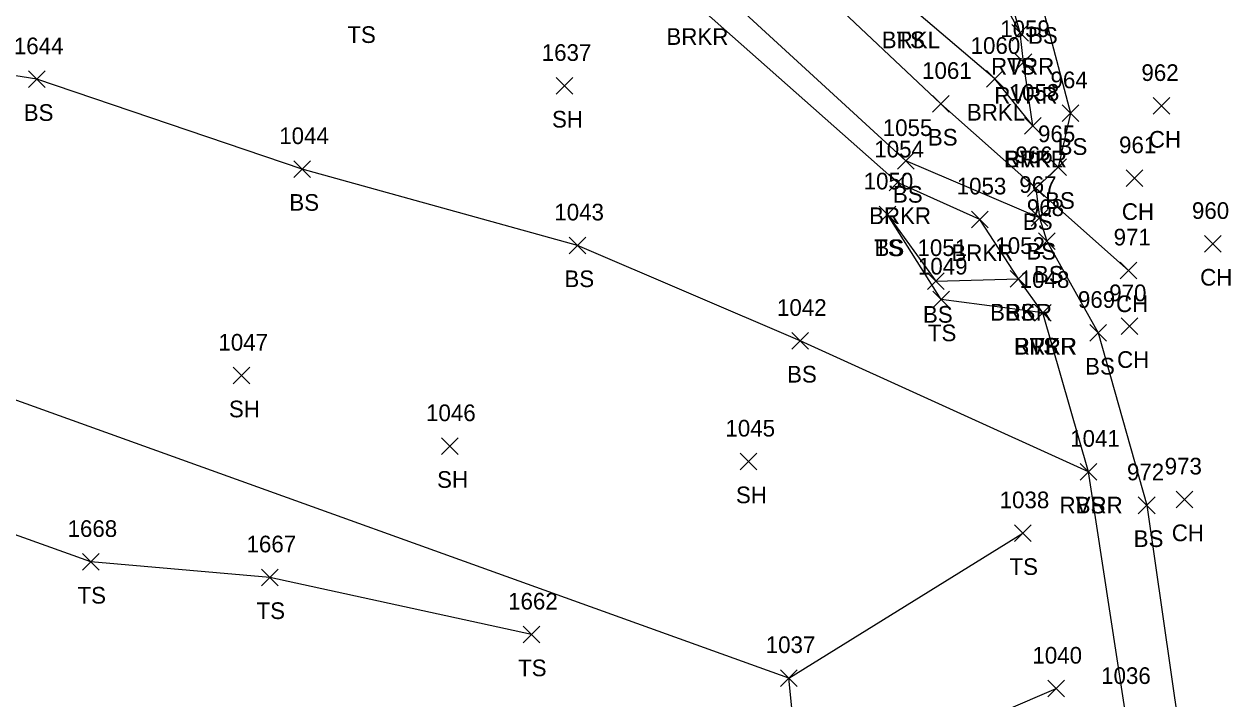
# Model space of a CAD drawing. Extents: x 1885914 to 1887218, y 756253 to 760620.
# Drawn here: x 1886519.5 to 1886664.7, y 759574 to 759655 of the extents above; entities that cross this region are included whole.
import ezdxf

# ---------------------------------------------------------------- set-up
doc = ezdxf.new("R2010")
doc.units = 0
for name, color, linetype in [('L_A', 7, 'Continuous'), ('L_I', 7, 'Continuous'), ('L_TIC', 7, 'Continuous'), ('LAWE', 7, 'Continuous'), ('LELB', 7, 'Continuous')]:
    doc.layers.add(name, color=color, linetype=linetype)

msp = doc.modelspace()

# ---------------------------------------------------------------- linework, layer by layer
at = {"layer": 'L_TIC'}
for points in [[(1886637.96, 759652.9), (1886639.96, 759654.9)], [(1886639.96, 759652.9), (1886637.96, 759654.9)], [(1886637.96, 759652.9), (1886639.96, 759654.9)], [(1886639.96, 759652.9), (1886637.96, 759654.9)], [(1886638.36, 759649.41), (1886640.36, 759651.41)], [(1886640.36, 759649.41), (1886638.36, 759651.41)], [(1886520.04, 759647.35), (1886522.04, 759649.35)], [(1886522.04, 759647.35), (1886520.04, 759649.35)], [(1886583.34, 759646.55), (1886585.34, 759648.55)], [(1886585.34, 759646.55), (1886583.34, 759648.55)], [(1886634.93, 759647.39), (1886636.93, 759649.39)], [(1886636.93, 759647.39), (1886634.93, 759649.39)], [(1886628.46, 759644.39), (1886630.46, 759646.39)], [(1886630.46, 759644.39), (1886628.46, 759646.39)], [(1886654.92, 759644.14), (1886656.92, 759646.14)], [(1886656.92, 759644.14), (1886654.92, 759646.14)], [(1886644.02, 759643.27), (1886646.02, 759645.27)], [(1886646.02, 759643.27), (1886644.02, 759645.27)], [(1886639.49, 759641.77), (1886641.49, 759643.77)], [(1886641.49, 759641.77), (1886639.49, 759643.77)], [(1886639.49, 759641.77), (1886641.49, 759643.77)], [(1886641.49, 759641.77), (1886639.49, 759643.77)], [(1886551.89, 759636.57), (1886553.89, 759638.57)], [(1886553.89, 759636.57), (1886551.89, 759638.57)], [(1886624.27, 759637.54), (1886626.27, 759639.54)], [(1886626.27, 759637.54), (1886624.27, 759639.54)], [(1886642.52, 759636.8), (1886644.52, 759638.8)], [(1886644.52, 759636.8), (1886642.52, 759638.8)], [(1886623.26, 759634.97), (1886625.26, 759636.97)], [(1886625.26, 759634.97), (1886623.26, 759636.97)], [(1886651.67, 759635.47), (1886653.67, 759637.47)], [(1886653.67, 759635.47), (1886651.67, 759637.47)], [(1886639.86, 759634.28), (1886641.86, 759636.28)], [(1886641.86, 759634.28), (1886639.86, 759636.28)], [(1886639.86, 759634.28), (1886641.86, 759636.28)], [(1886641.86, 759634.28), (1886639.86, 759636.28)], [(1886622.06, 759631.13), (1886624.06, 759633.13)], [(1886624.06, 759631.13), (1886622.06, 759633.13)], [(1886622.06, 759631.13), (1886624.06, 759633.13)], [(1886624.06, 759631.13), (1886622.06, 759633.13)], [(1886633.13, 759630.53), (1886635.13, 759632.53)], [(1886635.13, 759630.53), (1886633.13, 759632.53)], [(1886640.28, 759630.71), (1886642.28, 759632.71)], [(1886642.28, 759630.71), (1886640.28, 759632.71)], [(1886640.28, 759630.71), (1886642.28, 759632.71)], [(1886642.28, 759630.71), (1886640.28, 759632.71)], [(1886584.88, 759627.41), (1886586.88, 759629.41)], [(1886586.88, 759627.41), (1886584.88, 759629.41)], [(1886641.18, 759627.94), (1886643.18, 759629.94)], [(1886643.18, 759627.94), (1886641.18, 759629.94)], [(1886661.07, 759627.59), (1886663.07, 759629.59)], [(1886663.07, 759627.59), (1886661.07, 759629.59)], [(1886627.87, 759623.14), (1886629.87, 759625.14)], [(1886629.87, 759623.14), (1886627.87, 759625.14)], [(1886637.77, 759623.39), (1886639.77, 759625.39)], [(1886639.77, 759623.39), (1886637.77, 759625.39)], [(1886637.77, 759623.39), (1886639.77, 759625.39)], [(1886639.77, 759623.39), (1886637.77, 759625.39)], [(1886650.98, 759624.41), (1886652.98, 759626.41)], [(1886652.98, 759624.41), (1886650.98, 759626.41)], [(1886628.49, 759620.92), (1886630.49, 759622.92)], [(1886630.49, 759620.92), (1886628.49, 759622.92)], [(1886640.69, 759619.32), (1886642.69, 759621.32)], [(1886642.69, 759619.32), (1886640.69, 759621.32)], [(1886640.69, 759619.32), (1886642.69, 759621.32)], [(1886642.69, 759619.32), (1886640.69, 759621.32)], [(1886640.69, 759619.32), (1886642.69, 759621.32)], [(1886642.69, 759619.32), (1886640.69, 759621.32)], [(1886651.1, 759617.72), (1886653.1, 759619.72)], [(1886653.1, 759617.72), (1886651.1, 759619.72)], [(1886611.58, 759615.96), (1886613.58, 759617.96)], [(1886613.58, 759615.96), (1886611.58, 759617.96)], [(1886647.32, 759616.92), (1886649.32, 759618.92)], [(1886649.32, 759616.92), (1886647.32, 759618.92)], [(1886544.6, 759611.79), (1886546.6, 759613.79)], [(1886546.6, 759611.79), (1886544.6, 759613.79)], [(1886569.56, 759603.33), (1886571.56, 759605.33)], [(1886571.56, 759603.33), (1886569.56, 759605.33)], [(1886605.4, 759601.48), (1886607.4, 759603.48)], [(1886607.4, 759601.48), (1886605.4, 759603.48)], [(1886646.18, 759600.26), (1886648.18, 759602.26)], [(1886648.18, 759600.26), (1886646.18, 759602.26)], [(1886646.18, 759600.26), (1886648.18, 759602.26)], [(1886648.18, 759600.26), (1886646.18, 759602.26)], [(1886657.66, 759596.93), (1886659.66, 759598.93)], [(1886659.66, 759596.93), (1886657.66, 759598.93)], [(1886653.14, 759596.23), (1886655.14, 759598.23)], [(1886655.14, 759596.23), (1886653.14, 759598.23)], [(1886638.28, 759592.88), (1886640.28, 759594.88)], [(1886640.28, 759592.88), (1886638.28, 759594.88)], [(1886526.52, 759589.44), (1886528.52, 759591.44)], [(1886528.52, 759589.44), (1886526.52, 759591.44)], [(1886547.99, 759587.59), (1886549.99, 759589.59)], [(1886549.99, 759587.59), (1886547.99, 759589.59)], [(1886579.36, 759580.73), (1886581.36, 759582.73)], [(1886581.36, 759580.73), (1886579.36, 759582.73)], [(1886610.24, 759575.51), (1886612.24, 759577.51)], [(1886612.24, 759575.51), (1886610.24, 759577.51)], [(1886610.24, 759575.51), (1886612.24, 759577.51)], [(1886612.24, 759575.51), (1886610.24, 759577.51)], [(1886642.3, 759574.24), (1886644.3, 759576.24)], [(1886644.3, 759574.24), (1886642.3, 759576.24)]]:
    msp.add_lwpolyline(points, dxfattribs=at)
at = {"layer": 'LAWE'}
for points in [[(1886640.49, 759642.77), (1886639.36, 759650.41), (1886638.96, 759653.9), (1886632.66, 759676.07), (1886629.25, 759698.11), (1886627.43, 759722.42), (1886630.5, 759750.23), (1886628.11, 759765.28), (1886627.09, 759783.44), (1886625.27, 759802.03), (1886629.52, 759812.91), (1886630.27, 759842.49), (1886632.62, 759860.26), (1886629.59, 759874.2), (1886633.72, 759902.05), (1886645.92, 759929.12), (1886643.57, 759950.66), (1886647.93, 759967.68)], [(1886640.49, 759642.77), (1886635.93, 759648.39), (1886625.72, 759657.07), (1886610.91, 759666.24), (1886566.04, 759694.2), (1886558.03, 759693.43), (1886549.48, 759683.42), (1886541.76, 759683.05), (1886538.38, 759693.03), (1886535.18, 759703.57), (1886540.79, 759708.21), (1886545.85, 759715), (1886545.65, 759719.06), (1886543.13, 759722.74), (1886530.98, 759738.04), (1886525.52, 759742.88), (1886512.03, 759740.29)], [(1886641.69, 759620.32), (1886638.77, 759624.39), (1886634.13, 759631.53), (1886624.26, 759635.97), (1886599.96, 759657.47), (1886596.19, 759663.85)], [(1886679.54, 759389.71), (1886677.75, 759420.78), (1886679.05, 759444.6), (1886671.19, 759480.76), (1886664, 759509.38), (1886663.16, 759524.82), (1886651.51, 759572.8), (1886647.18, 759601.26), (1886641.69, 759620.32)]]:
    msp.add_lwpolyline(points, dxfattribs=at)
at = {"layer": 'LELB'}
for points in [[(1886651.59, 759963.58), (1886647.85, 759929.2), (1886639.89, 759913.67), (1886633.14, 759883.1), (1886633.96, 759851.09), (1886632.16, 759822.61), (1886631.66, 759800.6), (1886631.69, 759739.71), (1886631.53, 759709.44), (1886635.98, 759687.07), (1886641.47, 759657.6), (1886645.02, 759644.27), (1886643.52, 759637.8), (1886640.86, 759635.28), (1886641.28, 759631.71), (1886642.18, 759628.94), (1886648.32, 759617.92), (1886654.14, 759597.23), (1886659.93, 759557.18), (1886668.26, 759522.06), (1886683.34, 759437.14), (1886685.68, 759384.91)], [(1886638.96, 759653.9), (1886625.7, 759678.66), (1886616.18, 759693.78), (1886606.91, 759709.6), (1886593.74, 759732.8), (1886584.57, 759768.2), (1886579.84, 759785.39)], [(1886640.86, 759635.28), (1886629.46, 759645.39), (1886608.83, 759664.88), (1886565.88, 759693.24), (1886558.56, 759692.1), (1886549.76, 759681.84), (1886540.56, 759681.77), (1886535.74, 759692.33), (1886532.01, 759705), (1886538.81, 759708.82), (1886544.13, 759715.56), (1886544.53, 759718.92), (1886541.92, 759722.44), (1886529.87, 759737.67), (1886525.4, 759740.93), (1886512.72, 759738.63)], [(1886647.18, 759601.26), (1886612.58, 759616.96), (1886585.88, 759628.41), (1886552.89, 759637.57), (1886521.04, 759648.35), (1886499.66, 759651.75), (1886473.75, 759638.14), (1886464.33, 759634.19), (1886467.48, 759658.65), (1886468.81, 759680.84), (1886468.46, 759711.52)], [(1886641.28, 759631.71), (1886625.27, 759638.54), (1886601.69, 759660.25), (1886597.54, 759665.62)], [(1886640.86, 759635.28), (1886651.98, 759625.41)], [(1886641.69, 759620.32), (1886629.49, 759621.92), (1886623.06, 759632.13)], [(1886623.06, 759632.13), (1886628.87, 759624.14), (1886638.77, 759624.39)], [(1886611.24, 759576.51), (1886511.63, 759612.33), (1886487.59, 759618.45), (1886462.93, 759609.64)], [(1886580.36, 759581.73), (1886548.99, 759588.59), (1886527.52, 759590.44), (1886487.21, 759604.88), (1886460.19, 759599.17)], [(1886637.28, 759378.88), (1886638.5, 759417.22), (1886631.48, 759455.22), (1886628.32, 759478.77), (1886617.11, 759517.86), (1886611.24, 759576.51), (1886639.28, 759593.88)], [(1886632.05, 759478.37), (1886619.46, 759518.6), (1886618.63, 759564.67), (1886643.3, 759575.24)]]:
    msp.add_lwpolyline(points, dxfattribs=at)

# ---------------------------------------------------------------- texts
at = {"layer": 'L_A'}
for s, p in [('TS', (1886558.29, 759652.7)), ('BRKR', (1886596.55, 759652.47)), ('BRKL', (1886622.37, 759652.07)), ('TS', (1886624.13, 759652.07)), ('BS', (1886639.91, 759652.6)), ('RVRR', (1886635.48, 759648.9)), ('TS', (1886637.37, 759648.9)), ('RVRR', (1886635.87, 759645.41)), ('BS', (1886519.48, 759643.35)), ('BRKL', (1886632.58, 759643.39)), ('SH', (1886582.83, 759642.55)), ('BS', (1886627.9, 759640.39)), ('BS', (1886643.46, 759639.27)), ('CH', (1886654.4, 759640.14)), ('RVRR', (1886637, 759637.77)), ('BRKL', (1886637.13, 759637.77)), ('BS', (1886623.71, 759633.54)), ('BS', (1886551.33, 759632.57)), ('BS', (1886641.96, 759632.8)), ('BRKR', (1886620.85, 759630.97)), ('BS', (1886639.3, 759630.28)), ('BS', (1886639.3, 759630.28)), ('CH', (1886651.16, 759631.47)), ('TS', (1886621.47, 759627.13)), ('BS', (1886621.5, 759627.13)), ('BRKR', (1886630.72, 759626.53)), ('BS', (1886639.72, 759626.71)), ('BS', (1886639.72, 759626.71)), ('BS', (1886584.32, 759623.41)), ('BS', (1886640.62, 759623.94)), ('CH', (1886660.55, 759623.59)), ('CH', (1886650.47, 759620.41)), ('BS', (1886627.31, 759619.14)), ('BRKR', (1886635.36, 759619.39)), ('BS', (1886637.21, 759619.39)), ('TS', (1886627.9, 759616.92)), ('RVRR', (1886638.2, 759615.32)), ('BRKR', (1886638.28, 759615.32)), ('TS', (1886640.1, 759615.32)), ('BS', (1886646.76, 759612.92)), ('CH', (1886650.59, 759613.72)), ('BS', (1886611.02, 759611.96)), ('SH', (1886544.09, 759607.79)), ('SH', (1886569.05, 759599.33)), ('SH', (1886604.89, 759597.48)), ('RVRR', (1886643.69, 759596.26)), ('BS', (1886645.62, 759596.26)), ('CH', (1886657.15, 759592.93)), ('BS', (1886652.58, 759592.23)), ('TS', (1886637.69, 759588.88)), ('TS', (1886525.93, 759585.44)), ('TS', (1886547.4, 759583.59)), ('TS', (1886578.76, 759576.73))]:
    msp.add_text(s, height=2, dxfattribs=at).set_placement(p)
at = {"layer": 'L_I'}
for s, p in [('1059', (1886636.58, 759653.41)), ('1644', (1886518.3, 759651.35)), ('1060', (1886633.03, 759651.39)), ('1637', (1886581.6, 759650.55)), ('1061', (1886627.21, 759648.39)), ('962', (1886653.51, 759648.14)), ('964', (1886642.61, 759647.27)), ('1058', (1886637.71, 759645.77)), ('1058', (1886637.71, 759645.77)), ('1044', (1886550.12, 759640.57)), ('1055', (1886622.49, 759641.54)), ('965', (1886641.11, 759640.8)), ('961', (1886650.83, 759639.47)), ('1054', (1886621.48, 759638.97)), ('966', (1886638.4, 759638.28)), ('966', (1886638.4, 759638.28)), ('1050', (1886620.2, 759635.13)), ('1050', (1886620.2, 759635.13)), ('967', (1886638.87, 759634.71)), ('967', (1886638.87, 759634.71)), ('1053', (1886631.36, 759634.53)), ('968', (1886639.77, 759631.94)), ('1043', (1886583.11, 759631.41)), ('960', (1886659.57, 759631.59)), ('1052', (1886635.99, 759627.39)), ('1052', (1886635.99, 759627.39)), ('971', (1886650.18, 759628.41)), ('1051', (1886626.66, 759627.14)), ('1049', (1886626.71, 759624.92)), ('1048', (1886638.92, 759623.32)), ('1048', (1886638.92, 759623.32)), ('1048', (1886638.92, 759623.32)), ('970', (1886649.65, 759621.72)), ('969', (1886645.9, 759620.92)), ('1042', (1886609.81, 759619.96)), ('1047', (1886542.83, 759615.79)), ('1046', (1886567.73, 759607.33)), ('1045', (1886603.63, 759605.48)), ('1041', (1886644.97, 759604.26)), ('1041', (1886644.97, 759604.26)), ('972', (1886651.78, 759600.23)), ('973', (1886656.3, 759600.93)), ('1038', (1886636.51, 759596.88)), ('1668', (1886524.74, 759593.44)), ('1667', (1886546.2, 759591.59)), ('1662', (1886577.57, 759584.73)), ('1037', (1886608.46, 759579.51)), ('1037', (1886608.46, 759579.51)), ('1040', (1886640.44, 759578.24)), ('1036', (1886648.68, 759575.8))]:
    msp.add_text(s, height=2, dxfattribs=at).set_placement(p)

doc.saveas('drawing.dxf')
